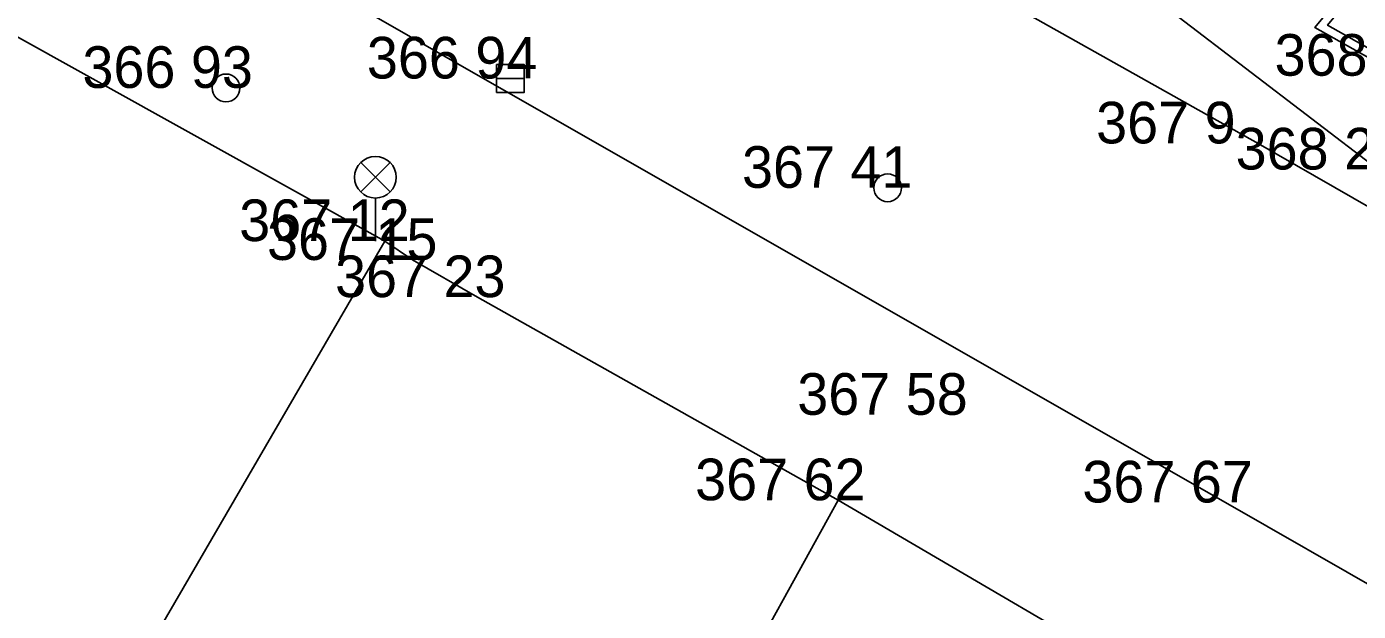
# Model space of a CAD drawing. Extents: x -688316 to -688024, y -973785 to -973591.
# Drawn here: x -688150.19 to -688126.22, y -973696.66 to -973686.13 of the extents above; entities that cross this region are included whole.
import ezdxf

# ---------------------------------------------------------------- set-up
doc = ezdxf.new("R2010")
doc.units = 0
for name, color, linetype in [('Vrstva 10', 7, 'Continuous'), ('Vrstva 27', 7, 'Continuous'), ('Vrstva 28_Verejne osvetleni', 7, 'Continuous'), ('Vrstva 3', 7, 'Continuous'), ('Vrstva 31', 7, 'Continuous'), ('Vrstva 33', 7, 'Continuous'), ('Vrstva 5', 7, 'Continuous'), ('Vrstva 6', 7, 'Continuous')]:
    doc.layers.add(name, color=color, linetype=linetype)

# ---------------------------------------------------------------- blocks, each defined once
blk = doc.blocks.new('LAO')
at = {"layer": 'Vrstva 33'}
for p, q in [((-2.65, 14.16), (2.65, 8.85)), ((-2.65, 8.85), (2.65, 14.16)), ((0, 0), (0, 7.75))]:
    blk.add_line(p, q, dxfattribs=at)
blk.add_circle((0, 11.5), 3.75, dxfattribs=at)
blk = doc.blocks.new('SP')
at = {"layer": 'Vrstva 31'}
blk.add_circle((0, 0), 2.5, dxfattribs=at)
blk = doc.blocks.new('VP')
at = {"layer": 'Vrstva 27'}
blk.add_line((-2.5, 0), (2.5, 0), dxfattribs=at)
blk.add_lwpolyline([(-2.5, -2.5), (2.5, -2.5), (2.5, 2.5), (-2.5, 2.5)], close=True, dxfattribs=at)
blk = doc.blocks.new('SV')
at = {"layer": 'Vrstva 28_Verejne osvetleni'}
blk.add_circle((0, 0), 2.5, dxfattribs=at)

msp = doc.modelspace()

# ---------------------------------------------------------------- linework, layer by layer
at = {"layer": 'Vrstva 10'}
for p, q in [((-688128.61, -973694.7), (-688146.68, -973684.36)), ((-688133.04, -973685.41), (-688128.02, -973688.23)), ((-688113.84, -973703.18), (-688128.61, -973694.7))]:
    msp.add_line(p, q, dxfattribs=at)
for points in [[(-688123.045, -973684.829), (-688123.471, -973684.566), (-688125.098, -973687.211), (-688126.999, -973686.143), (-688125.809, -973684.693), (-688131.727, -973681.371)], [(-688123.52, -973684.36), (-688125.15, -973687.01), (-688126.77, -973686.1), (-688125.58, -973684.65), (-688130.78, -973681.73)], [(-688117.05, -973688.61), (-688118.95, -973691.55), (-688122.71, -973689.32), (-688123.6, -973690.77), (-688125.86, -973688.7), (-688129.44, -973685.96), (-688133.06, -973683.78)], [(-688128.02, -973688.23), (-688123.6, -973690.77), (-688122.97, -973691.13)]]:
    msp.add_lwpolyline(points, dxfattribs=at)
at = {"layer": 'Vrstva 5'}
for p, q in [((-688150.66, -973686.14), (-688143.74, -973689.99)), ((-688153.55, -973706.89), (-688143.74, -973689.99)), ((-688143.24, -973690.33), (-688143.74, -973689.99)), ((-688145.05, -973711.82), (-688135.58, -973694.66))]:
    msp.add_line(p, q, dxfattribs=at)
msp.add_lwpolyline([(-688129.02, -973698.5), (-688135.58, -973694.66), (-688142.07, -973691)], dxfattribs=at)
at = {"layer": 'Vrstva 6'}
msp.add_line((-688142.07, -973691), (-688143.24, -973690.33), dxfattribs=at)

# ---------------------------------------------------------------- block references
at = {"layer": 'Vrstva 27', "xscale": 0.1, "yscale": 0.10000000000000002}
msp.add_blockref('VP', (-688141.48, -973687.06), dxfattribs=at)
at = {"layer": 'Vrstva 28_Verejne osvetleni', "xscale": 0.1, "yscale": 0.10000000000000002}
msp.add_blockref('SV', (-688134.69, -973689.03), dxfattribs=at)
at = {"layer": 'Vrstva 31', "xscale": 0.1, "yscale": 0.10000000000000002}
msp.add_blockref('SP', (-688146.6, -973687.23), dxfattribs=at)
at = {"layer": 'Vrstva 33', "xscale": 0.1, "yscale": 0.10000000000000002}
msp.add_blockref('LAO', (-688143.91, -973689.99), dxfattribs=at)

# ---------------------------------------------------------------- texts
at = {"layer": 'Vrstva 3'}
for s, p in [('366 94 ', (-688144.063, -973687.06)), ('366 94 ', (-688144.063, -973687.06)), ('366 94 ', (-688144.063, -973687.06)), ('366 94 ', (-688144.063, -973687.06)), ('366 94 ', (-688144.063, -973687.06)), ('366 94 ', (-688144.063, -973687.06)), ('366 94 ', (-688144.063, -973687.06)), ('368 64 ', (-688127.725, -973687.01)), ('368 64 ', (-688127.725, -973687.01)), ('368 64 ', (-688127.725, -973687.01)), ('368 64 ', (-688127.725, -973687.01)), ('368 64 ', (-688127.725, -973687.01)), ('368 64 ', (-688127.725, -973687.01)), ('368 64 ', (-688127.725, -973687.01)), ('366 93 ', (-688149.183, -973687.23)), ('366 93 ', (-688149.183, -973687.23)), ('366 93 ', (-688149.183, -973687.23)), ('366 93 ', (-688149.183, -973687.23)), ('366 93 ', (-688149.183, -973687.23)), ('366 93 ', (-688149.183, -973687.23)), ('366 93 ', (-688149.183, -973687.23)), ('367 9  ', (-688130.937, -973688.23)), ('367 9  ', (-688130.937, -973688.23)), ('367 9  ', (-688130.937, -973688.23)), ('367 9  ', (-688130.937, -973688.23)), ('367 9  ', (-688130.937, -973688.23)), ('367 9  ', (-688130.937, -973688.23)), ('367 9  ', (-688130.937, -973688.23)), ('368 26 ', (-688128.426, -973688.7)), ('368 26 ', (-688128.426, -973688.7)), ('368 26 ', (-688128.426, -973688.7)), ('368 26 ', (-688128.426, -973688.7)), ('368 26 ', (-688128.426, -973688.7)), ('368 26 ', (-688128.426, -973688.7)), ('368 26 ', (-688128.426, -973688.7)), ('367 41 ', (-688137.311, -973689.03)), ('367 41 ', (-688137.311, -973689.03)), ('367 41 ', (-688137.311, -973689.03)), ('367 41 ', (-688137.311, -973689.03)), ('367 41 ', (-688137.311, -973689.03)), ('367 41 ', (-688137.311, -973689.03)), ('367 41 ', (-688137.311, -973689.03)), ('367 12 ', (-688146.361, -973689.99)), ('367 12 ', (-688146.361, -973689.99)), ('367 12 ', (-688146.361, -973689.99)), ('367 12 ', (-688146.361, -973689.99)), ('367 12 ', (-688146.361, -973689.99)), ('367 12 ', (-688146.361, -973689.99)), ('367 12 ', (-688146.361, -973689.99)), ('367 15 ', (-688145.861, -973690.33)), ('367 15 ', (-688145.861, -973690.33)), ('367 15 ', (-688145.861, -973690.33)), ('367 15 ', (-688145.861, -973690.33)), ('367 15 ', (-688145.861, -973690.33)), ('367 15 ', (-688145.861, -973690.33)), ('367 15 ', (-688145.861, -973690.33)), ('367 23 ', (-688144.636, -973691)), ('367 23 ', (-688144.636, -973691)), ('367 23 ', (-688144.636, -973691)), ('367 23 ', (-688144.636, -973691)), ('367 23 ', (-688144.636, -973691)), ('367 23 ', (-688144.636, -973691)), ('367 23 ', (-688144.636, -973691)), ('367 58 ', (-688136.316, -973693.12)), ('367 58 ', (-688136.316, -973693.12)), ('367 58 ', (-688136.316, -973693.12)), ('367 58 ', (-688136.316, -973693.12)), ('367 58 ', (-688136.316, -973693.12)), ('367 58 ', (-688136.316, -973693.12)), ('367 58 ', (-688136.316, -973693.12)), ('367 62 ', (-688138.155, -973694.66)), ('367 62 ', (-688138.155, -973694.66)), ('367 62 ', (-688138.155, -973694.66)), ('367 62 ', (-688138.155, -973694.66)), ('367 62 ', (-688138.155, -973694.66)), ('367 62 ', (-688138.155, -973694.66)), ('367 62 ', (-688138.155, -973694.66)), ('367 67 ', (-688131.185, -973694.7)), ('367 67 ', (-688131.185, -973694.7)), ('367 67 ', (-688131.185, -973694.7)), ('367 67 ', (-688131.185, -973694.7)), ('367 67 ', (-688131.185, -973694.7)), ('367 67 ', (-688131.185, -973694.7)), ('367 67 ', (-688131.185, -973694.7))]:
    msp.add_text(s, height=0.75, dxfattribs=at).set_placement(p)

doc.saveas('drawing.dxf')
